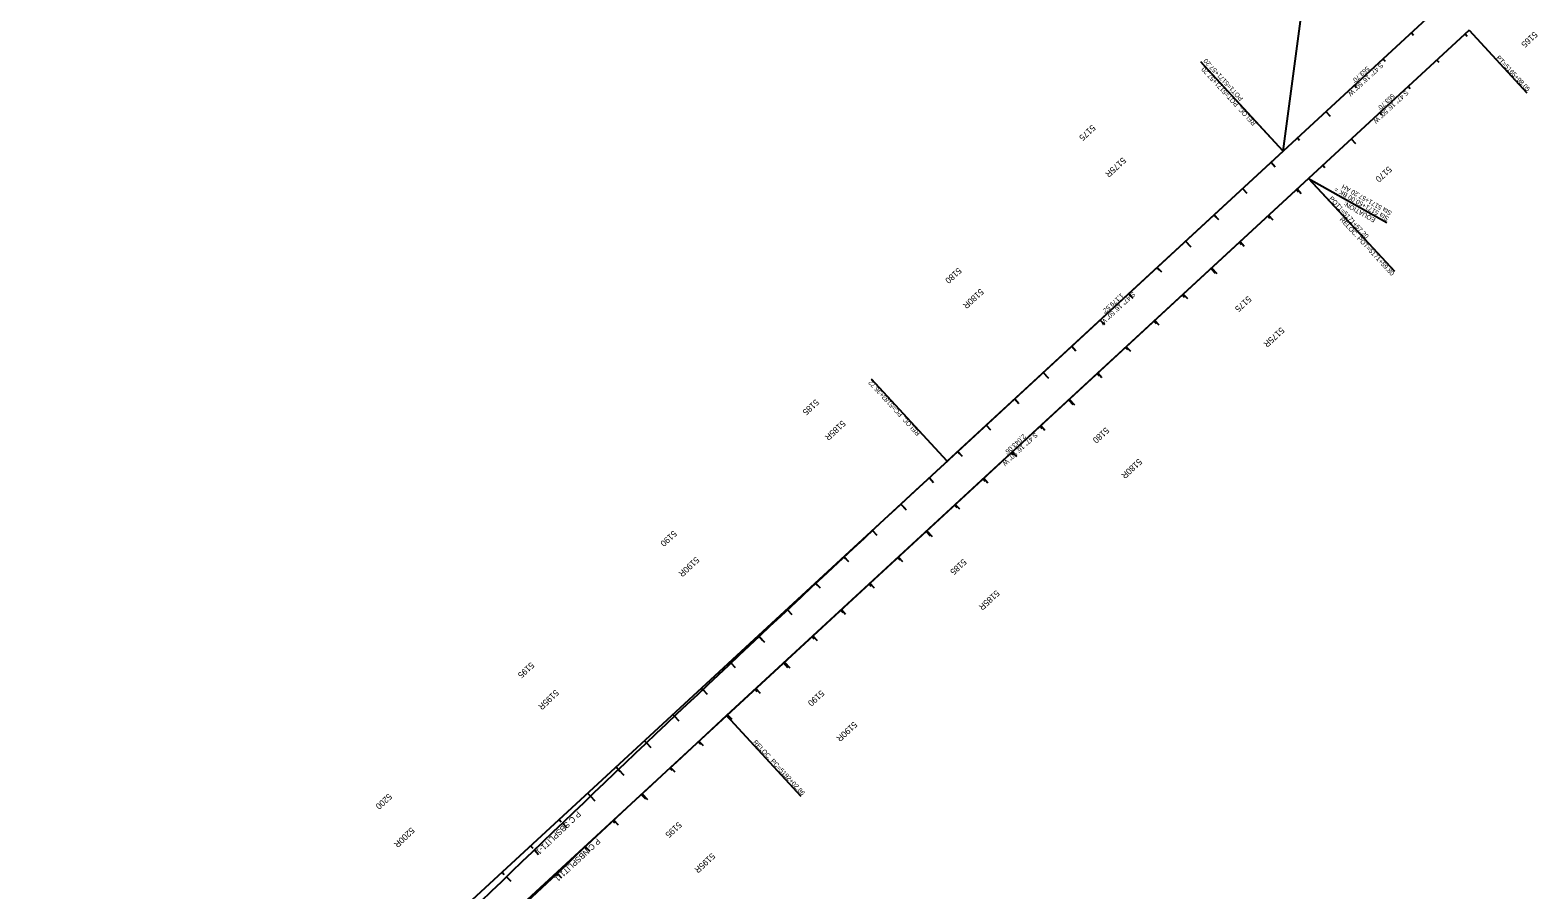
# Model space of a CAD drawing. Extents: x 2160877 to 2175861, y 601747 to 617724.
# Drawn here: x 2168975 to 2172864, y 611869 to 614087 of the extents above; entities that cross this region are included whole.
import ezdxf

# ---------------------------------------------------------------- set-up
doc = ezdxf.new("R2010")
doc.units = 0
for name, color, linetype in [('RD_HC_Cl', 7, 'Continuous'), ('RD_HC_CL_Rel', 7, 'Continuous'), ('RD_HC_Data', 7, 'Continuous'), ('RD_HC_Data_Rel', 7, 'Continuous'), ('RD_HC_Data_Tic', 7, 'Continuous'), ('RD_HC_Data_Tic_Rel', 7, 'Continuous'), ('RD_HC_TX_Rel_Sta50', 7, 'Continuous'), ('RD_HC_TX_Rel_StaOther', 7, 'Continuous'), ('RD_HC_TX_StaOther', 7, 'Continuous')]:
    doc.layers.add(name, color=color, linetype=linetype)

msp = doc.modelspace()

# ---------------------------------------------------------------- linework, layer by layer
at = {"layer": 'RD_HC_Cl'}
for p, q in [((2172621.5, 614157.6), (2172207.3, 613775.1)), ((2172686.6, 614087), (2172272.5, 613704.6)), ((2172207.3, 613775.1), (2163672.2, 605893.8)), ((2172272.5, 613704.6), (2163737.4, 605823.3))]:
    msp.add_line(p, q, dxfattribs=at)
at = {"layer": 'RD_HC_CL_Rel'}
for p, q in [((2172207.3, 613775.1), (2171340.7, 612974.9)), ((2172272.5, 613704.6), (2170771.4, 612318.6))]:
    msp.add_line(p, q, dxfattribs=at)
for centre, radius in [((2222221.5, 557873.6), 75000), ((2219616.9, 559421.3), 72000)]:
    msp.add_arc(centre, radius, 132.719474, 134.517591, dxfattribs=at)
at = {"layer": 'RD_HC_Data'}
for p, q in [((2172207.3, 613775.1), (2172285.1, 614364.1)), ((2172686.6, 614087), (2172836, 613925.2)), ((2172207.3, 613775.1), (2171994.9, 614005.2)), ((2172272.5, 613704.6), (2172474.3, 613590.3)), ((2172272.5, 613704.6), (2172421.7, 613543))]:
    msp.add_line(p, q, dxfattribs=at)
at = {"layer": 'RD_HC_Data_Rel'}
for p, q in [((2172207.3, 613775.1), (2171998.5, 614001.3)), ((2172272.5, 613704.6), (2172493.8, 613464.9)), ((2171340.7, 612974.9), (2171145.2, 613186.7)), ((2170771.4, 612318.6), (2170963.2, 612110.9))]:
    msp.add_line(p, q, dxfattribs=at)
at = {"layer": 'RD_HC_Data_Tic'}
for p, q in [((2172537.9, 614080.4), (2172543.4, 614074.5)), ((2172676.5, 614077.7), (2172682, 614071.9)), ((2172464.5, 614012.6), (2172469.9, 614006.7)), ((2172603.1, 614009.9), (2172608.5, 614004)), ((2172391, 613944.7), (2172396.4, 613938.9)), ((2172529.6, 613942.1), (2172535, 613936.2)), ((2172317.5, 613876.9), (2172328.4, 613865.1)), ((2172456.1, 613874.2), (2172461.5, 613868.3)), ((2172244.1, 613809.1), (2172249.5, 613803.2)), ((2172382.7, 613806.4), (2172393.5, 613794.6)), ((2172175.9, 613746.1), (2172181.3, 613740.2)), ((2172309.2, 613738.5), (2172314.6, 613732.7)), ((2172102.4, 613678.3), (2172107.8, 613672.4)), ((2172241, 613675.6), (2172246.4, 613669.7)), ((2172028.9, 613610.4), (2172034.4, 613604.5)), ((2172167.5, 613607.7), (2172173, 613601.9)), ((2171955.5, 613542.6), (2171966.3, 613530.8)), ((2172094.1, 613539.9), (2172099.5, 613534)), ((2171882, 613474.7), (2171887.4, 613468.9)), ((2172020.6, 613472.1), (2172031.5, 613460.3)), ((2171808.5, 613406.9), (2171814, 613401)), ((2171947.1, 613404.2), (2171952.6, 613398.3)), ((2171735.1, 613339.1), (2171740.5, 613333.2)), ((2171873.7, 613336.4), (2171879.1, 613330.5)), ((2171661.6, 613271.2), (2171667, 613265.3)), ((2171800.2, 613268.5), (2171805.6, 613262.7)), ((2171588.1, 613203.4), (2171599, 613191.6)), ((2171726.7, 613200.7), (2171732.2, 613194.8)), ((2171514.7, 613135.5), (2171520.1, 613129.7)), ((2171653.3, 613132.8), (2171664.1, 613121.1)), ((2171441.2, 613067.7), (2171446.6, 613061.8)), ((2171579.8, 613065), (2171585.2, 613059.1)), ((2171367.7, 612999.9), (2171373.2, 612994)), ((2171506.3, 612997.2), (2171511.8, 612991.3)), ((2171294.3, 612932), (2171299.7, 612926.1)), ((2171432.9, 612929.3), (2171438.3, 612923.4)), ((2171220.8, 612864.2), (2171231.6, 612852.4)), ((2171359.4, 612861.5), (2171364.8, 612855.6)), ((2171147.3, 612796.3), (2171152.7, 612790.5)), ((2171285.9, 612793.6), (2171296.8, 612781.9)), ((2171073.9, 612728.5), (2171079.3, 612722.6)), ((2171212.4, 612725.8), (2171217.9, 612719.9)), ((2171000.4, 612660.7), (2171005.8, 612654.8)), ((2171139, 612658), (2171144.4, 612652.1)), ((2170926.9, 612592.8), (2170932.3, 612586.9)), ((2171065.5, 612590.1), (2171070.9, 612584.2)), ((2170853.4, 612525), (2170864.3, 612513.2)), ((2170992, 612522.3), (2170997.5, 612516.4)), ((2170780, 612457.1), (2170785.4, 612451.3)), ((2170918.6, 612454.4), (2170929.4, 612442.7)), ((2170706.5, 612389.3), (2170711.9, 612383.4)), ((2170845.1, 612386.6), (2170850.5, 612380.7)), ((2170633, 612321.4), (2170638.5, 612315.6)), ((2170771.6, 612318.8), (2170777.1, 612312.9)), ((2170559.6, 612253.6), (2170565, 612247.7)), ((2170698.2, 612250.9), (2170703.6, 612245)), ((2170486.1, 612185.8), (2170497, 612174)), ((2170624.7, 612183.1), (2170630.1, 612177.2)), ((2170412.6, 612117.9), (2170418.1, 612112)), ((2170551.2, 612115.2), (2170562.1, 612103.5)), ((2170339.2, 612050.1), (2170344.6, 612044.2)), ((2170477.8, 612047.4), (2170483.2, 612041.5)), ((2170265.7, 611982.2), (2170271.1, 611976.4)), ((2170404.3, 611979.6), (2170409.7, 611973.7)), ((2170192.2, 611914.4), (2170197.7, 611908.5)), ((2170330.8, 611911.7), (2170336.3, 611905.8))]:
    msp.add_line(p, q, dxfattribs=at)
at = {"layer": 'RD_HC_Data_Tic_Rel'}
for p, q in [((2172175.9, 613746.1), (2172186.7, 613734.4)), ((2172102.4, 613678.3), (2172113.3, 613666.5)), ((2172242.9, 613677.3), (2172253.8, 613665.6)), ((2172028.9, 613610.4), (2172039.8, 613598.7)), ((2172169.4, 613609.5), (2172180.3, 613597.7)), ((2171955.5, 613542.6), (2171969, 613527.9)), ((2172096, 613541.7), (2172106.8, 613529.9)), ((2171882, 613474.7), (2171892.9, 613463)), ((2172022.5, 613473.8), (2172036.1, 613459.1)), ((2171808.5, 613406.9), (2171819.4, 613395.1)), ((2171949, 613406), (2171959.9, 613394.2)), ((2171735.1, 613339.1), (2171745.9, 613327.3)), ((2171875.6, 613338.1), (2171886.4, 613326.4)), ((2171661.6, 613271.2), (2171672.5, 613259.5)), ((2171802.1, 613270.3), (2171813, 613258.5)), ((2171588.1, 613203.4), (2171601.7, 613188.7)), ((2171728.6, 613202.5), (2171739.5, 613190.7)), ((2171514.7, 613135.5), (2171525.5, 613123.8)), ((2171655.2, 613134.6), (2171668.7, 613119.9)), ((2171441.2, 613067.7), (2171452.1, 613055.9)), ((2171581.7, 613066.8), (2171592.6, 613055)), ((2171367.7, 612999.9), (2171378.6, 612988.1)), ((2171508.2, 612998.9), (2171519.1, 612987.2)), ((2171294.3, 612932), (2171305.1, 612920.2)), ((2171434.8, 612931.1), (2171445.6, 612919.3)), ((2171220.9, 612864), (2171234.5, 612849.4)), ((2171361.3, 612863.2), (2171372.2, 612851.5)), ((2171147.6, 612796), (2171158.5, 612784.3)), ((2171287.8, 612795.4), (2171301.4, 612780.7)), ((2171074.5, 612727.8), (2171085.4, 612716.1)), ((2171214.4, 612727.6), (2171225.2, 612715.8)), ((2171001.4, 612659.6), (2171012.3, 612647.9)), ((2171140.9, 612659.7), (2171151.7, 612648)), ((2171067.4, 612591.9), (2171078.3, 612580.1)), ((2170928.4, 612591.3), (2170939.3, 612579.6)), ((2170855.4, 612522.8), (2170869.1, 612508.2)), ((2170994, 612524), (2171004.8, 612512.3)), ((2170782.6, 612454.3), (2170793.6, 612442.6)), ((2170920.5, 612456.2), (2170934.1, 612441.5)), ((2170709.9, 612385.6), (2170720.9, 612374)), ((2170847, 612388.4), (2170857.9, 612376.6)), ((2170773.5, 612320.5), (2170784.4, 612308.8)), ((2170637.3, 612316.9), (2170648.3, 612305.3)), ((2170564.7, 612248.1), (2170575.7, 612236.5)), ((2170700.1, 612252.6), (2170711, 612240.9)), ((2170492.3, 612179.2), (2170506.1, 612164.7)), ((2170626.8, 612184.6), (2170637.7, 612172.9)), ((2170419.9, 612110.1), (2170431, 612098.6)), ((2170553.6, 612116.5), (2170567.2, 612101.9)), ((2170480.4, 612048.4), (2170491.3, 612036.7)), ((2170347.6, 612041), (2170358.7, 612029.5)), ((2170275.5, 611971.8), (2170286.5, 611960.3)), ((2170407.4, 611980.1), (2170418.3, 611968.4)), ((2170203.4, 611902.5), (2170214.5, 611891)), ((2170334.4, 611911.7), (2170345.4, 611900))]:
    msp.add_line(p, q, dxfattribs=at)

# ---------------------------------------------------------------- texts
at = {"layer": 'RD_HC_Data'}
for s, rotation, p in [('POT1=5171+57.20', 132.7195, (2172104.7, 613911.1)), ('PT=5165+98.05', 312.7195, (2172755.9, 614014.9)), ('Sta 5171+57.20 AH', 150.4677, (2172488.7, 613618.3)), ('POT1=5171+57.20', 312.7195, (2172324.6, 613651.5)), ('Sta 5171+50.00 BK = ', 150.4677, (2172480.8, 613604.4)), ('EQUATION:', 150.4677, (2172446.6, 613600.5))]:
    msp.add_text(s, height=12, rotation=rotation, dxfattribs=at).set_placement(p)
at = {"layer": 'RD_HC_Data_Rel'}
for s, height, rotation, p in [('RELOC. POT=5171+57.20', 12, 132.7195, (2172138, 613847.3)), ('RELOC. POT=5171+59.80', 12, 312.7195, (2172351.8, 613597.6)), ('RELOC. PC=5183+36.72', 12, 132.7195, (2171271.4, 613047.1)), ('RELOC. PC=5192+02.86', 12, 312.7195, (2170838.9, 612248.9)), ('P C SBSPLIT1-1', 15, 223.5528, (2170386.8, 612072.9)), ('P C NBSPLIT1-1', 15, 222.7536, (2170437.4, 612002.5))]:
    msp.add_text(s, height=height, rotation=rotation, dxfattribs=at).set_placement(p)
at = {"layer": 'RD_HC_TX_Rel_Sta50'}
for s, rotation, p in [('5175R', 222.7195, (2171792.7, 613760.1)), ('5180R', 222.7195, (2171425.6, 613421.1)), ('5175R', 222.7195, (2172201.2, 613321.6)), ('5185R', 222.8442, (2171069.3, 613081.3)), ('5180R', 222.7195, (2171834.1, 612982.6)), ('5190R', 223.2262, (2170691.9, 612729.3)), ('5185R', 222.7195, (2171466.5, 612643.2)), ('5195R', 223.6082, (2170329.4, 612386.5)), ('5190R', 222.7195, (2171099.4, 612304.2)), ('5200R', 223.9901, (2169957.2, 612031.3)), ('5195R', 222.9559, (2170732.8, 611965))]:
    msp.add_text(s, height=16, rotation=rotation, dxfattribs=at).set_placement(p)
at = {"layer": 'RD_HC_TX_Rel_StaOther'}
for s, p in [('S 47%%d 16\' 50" W', (2171819.1, 613412.6)), ("1,179.52'", (2171788.7, 613409)), ('S 47%%d 16\' 50" W', (2171567, 613049.2)), ("2,043.06'", (2171536.6, 613045.6))]:
    msp.add_text(s, height=12, rotation=222.7195, dxfattribs=at).set_placement(p)
at = {"layer": 'RD_HC_TX_StaOther'}
for s, height, rotation, p in [('5165', 16, 223.1104, (2172854.4, 614084.7)), ('S 47%%d 16\' 50" W', 12, 222.7195, (2172458.6, 614003.1)), ("563.70'", 12, 222.7195, (2172423, 613994.7)), ('S 47%%d 16\' 50" W', 12, 222.7195, (2172523.8, 613932.6)), ("563.70'", 12, 222.7195, (2172488.2, 613924.2)), ('5175', 16, 222.7195, (2171714, 613844.1)), ('5170', 16, 222.7195, (2172478.5, 613737)), ('5180', 16, 222.7195, (2171368.6, 613475.5)), ('5175', 16, 222.7195, (2172116.1, 613402.3)), ('5185', 16, 222.7195, (2171000.9, 613136)), ('5180', 16, 222.7195, (2171749.1, 613063.5)), ('5190', 16, 222.7195, (2170633.9, 612797.1)), ('5185', 16, 222.7195, (2171381.4, 612723.9)), ('5195', 16, 222.7195, (2170266.2, 612457.5)), ('5190', 16, 222.7195, (2171014.4, 612385)), ('5200', 16, 222.7195, (2169899.3, 612118.7)), ('5195', 16, 222.7195, (2170646.7, 612045.5))]:
    msp.add_text(s, height=height, rotation=rotation, dxfattribs=at).set_placement(p)

doc.saveas('drawing.dxf')
